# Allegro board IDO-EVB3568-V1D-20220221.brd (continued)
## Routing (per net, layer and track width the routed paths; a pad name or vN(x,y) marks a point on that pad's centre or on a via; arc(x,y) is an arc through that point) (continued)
MIPI_DSI_TX1_D2P: length 65.1
  TOP w0.102: v2(55.63,66.04) 55.88,65.79 61.91,65.79 64.17,68.05 65.56,68.05 66.77,69.26 66.77,69.37 66.39,69.76 M5.131
  BOTTOM w0.102: J23.23 55.5,22.32 55.64,22.46 55.64,23.49 55.52,23.61 D57.7 D57.4 55.52,25.46 55.65,25.6 55.65,25.94 54.86,26.73 54.86,33.5 55.12,33.76 56.13,33.76 56.26,33.88 56.26,34.19 56.13,34.32 55.15,34.32 54.89,34.58 54.89,35.02 55.15,35.28 56.17,35.28 56.41,35.53 56.41,40.29 52.35,44.36 52.35,61.87 54.86,64.39 54.86,65.41 55.27,65.81 55.39,65.81 v2(55.63,66.04)
MIPI_DSI_TX1_D3N: length 64.6
  TOP w0.102: v2(54.36,64.42) 54.6,64.67 62.32,64.67 64.61,66.95 66.95,66.95 69,69 69,69.34 69.39,69.73 M5.128
  BOTTOM w0.102: J23.21 54.5,22.32 54.37,22.46 54.37,23.46 54.52,23.61 D57.9 D57.2 54.52,25.46 54.38,25.6 54.38,35.2 55.88,36.7 55.88,40.07 51.79,44.16 51.79,62.52 53.94,64.67 54.11,64.67 v2(54.36,64.42)
MIPI_DSI_TX1_D3P: length 64.6
  TOP w0.102: M5.129 68.39,69.69 68.77,69.3 68.77,69.1 66.86,67.18 64.52,67.18 62.23,64.9 54.6,64.9 v2(54.36,65.14)
  BOTTOM w0.102: v2(54.36,65.14) 54.11,64.9 53.85,64.9 51.56,62.61 51.56,44.07 55.65,39.98 55.65,36.8 54.15,35.3 54.15,25.6 54.02,25.46 D57.1 D57.10 54.02,23.61 54.14,23.49 54.14,22.46 54.01,22.32 J23.20
MIPI_DSI_TX1_RST: length 6.6
  BOTTOM w0.254: R119.2 62.44,27.39 62.65,27.18 C125.2 62,25.9 J23.36
MIPI_TX0_BL_PWM5: length 4.9
  TOP w0.127: U15.4 14.7,23.29 v2(13.77,23.29)
  BOTTOM w0.127: v2(13.77,23.29) 12.16,23.29 R102.2 R105.1
MIPI_TX1_BL_PWM4: length 2.8
  BOTTOM w0.127: R108.2 R116.1 40.85,34.04 40.93,33.96 U16.4
MPU6500_AD0: length 2.8
  BOTTOM w0.127: 66.4,41.86 R323.2 ; 66.4,41.86 R324.1 ; 66.4,41.86 65.81,41.28 U35.9
NSD_CD: length 6.6
  TOP w0.127: R24.2 118.87,17.96 D8.1 118.84,16.47 119.54,16.47 120.13,15.89 J3.9
PCA9539_A0: length 5.2
  BOTTOM w0.127: U38.21 80.74,44.83 80.74,44.83 R366.1 80.31,44.81 79.76,44.26 78.5,44.26 78.13,44.63 R364.2
PCA9539_A1: length 6.3
  BOTTOM w0.127: R363.2 94.44,48.28 94.07,48.65 92.9,48.65 92.41,48.16 R365.1 91.98,48.13 91.69,47.85 91.69,46.95 90.88,46.13 U38.2
PCA9539_I2C_SCL: length 2.8
  BOTTOM w0.127: R344.2 80.74,45.85 81.11,45.48 U38.22
PCA9539_I2C_SDA: length 2.9
  BOTTOM w0.127: R343.2 80.77,46.86 81.5,46.13 U38.23
PCA9539_INT: length 2.8
  BOTTOM w0.127: U38.1 88.6,46.78 88.44,46.94 R345.2
PCA9539_INT_GPIO4_C4: length 40.8
  TOP w0.127: v2(85.45,37.72) 85.45,35.41 78.87,28.83 70.48,28.83 69.6,27.94 67.31,27.94 65.39,26.02 M5.29
  BOTTOM w0.127: R345.1 87.25,48.13 84.71,45.59 84.71,38.46 v2(85.45,37.72)
PCA9539_IO0_0: length 81.1
  TOP w0.127: R36.1 47.17,78.94 50.55,75.56 v2(51.31,75.56) ; v2(85.1,44.7) 84.71,45.1 84.71,51.56 84.58,51.69 84.58,53.34 85.34,54.1 85.34,61.59 84.33,62.61 77.22,62.61 75.16,64.67 v2(71.04,64.67) ; v2(51.31,73.29) 51.43,73.17 65.55,73.17 66.67,74.3 69.71,74.3 v2(69.85,74.43)
  TOP w0.203: U5.4 48.05,80.44 R36.1
  BOTTOM w0.127: R353.1 92.41,46.08 91.16,44.83 U38.4 85.62,44.83 85.5,44.7 v2(85.1,44.7) ; v2(69.85,74.43) 70.71,73.57 70.71,65 v2(71.04,64.67) ; v2(51.31,73.29) v2(51.31,75.56)
PCA9539_IO0_1: length 18.6
  TOP w0.127: v2(84.61,53.93) 84.33,53.65 84.33,51.54 84.45,51.41 84.45,44.72 v2(85.1,44.07)
  BOTTOM w0.127: R352.1 91.98,45.09 91.08,44.18 U38.5 85.61,44.18 85.5,44.07 v2(85.1,44.07) ; R39.1 v2(84.61,53.93)
PCA9539_IO0_2: length 62
  TOP w0.127: v2(71.5,64.14) 71.78,64.41 75.03,64.41 77.09,62.36 84.2,62.36 85.09,61.47 85.09,55.24 83.95,54.1 83.95,51.56 84.2,51.31 84.2,44.34 v2(85.1,43.43)
  BOTTOM w0.127: v2(71.5,64.14) 73.41,66.04 73.41,73.94 75.77,76.3 75.77,77.98 R40.1 73.06,80.69 U6.4 ; v2(85.1,43.43) 85.5,43.43 85.59,43.53 U38.6 91.44,43.53 91.98,44.07 R351.1
PCA9539_IO0_3: length 54.2
  TOP w0.127: U7.4 80.83,80.37 80.95,80.24 v2(82.4,80.24) ; v2(82.42,59.56) 83.57,58.42 83.57,51.56 83.95,51.18 83.95,43.95 v2(85.1,42.8)
  BOTTOM w0.127: R42.1 81.71,80.01 82.17,80.01 82.27,80.11 ; v2(82.42,59.56) 84.2,61.34 84.2,64.9 85.47,66.17 85.47,67.82 86.49,68.83 86.49,75.31 85.85,75.95 82.93,75.95 82.27,76.61 82.27,80.11 ; v2(85.1,42.8) 85.5,42.8 85.58,42.88 U38.7 91.81,42.88 91.98,43.05 R350.1 ; 82.27,80.11 v2(82.4,80.24)
PCA9539_IO0_4: length 50.7
  TOP w0.127: v2(85.1,42.16) 83.69,43.57 83.69,51.05 82.72,52.03 82.72,58.63 v2(82.42,58.93)
  BOTTOM w0.127: R349.1 91.95,42.04 91.75,42.23 U38.8 85.56,42.23 85.5,42.16 v2(85.1,42.16) ; v2(82.42,58.93) 84.45,60.96 84.45,64.77 85.72,66.04 85.72,67.63 86.74,68.65 86.74,74.8 88.19,76.25 88.19,78.95 88.17,78.98 R47.1 88.17,79.47 87.06,80.58 U9.4
PCA9539_IO0_5: length 53.1
  TOP w0.127: v2(84.99,51.84) 84.99,45.44 85.5,44.93 85.5,41.92 v2(85.11,41.53) ; U10.4 95.2,79.34 R52.1 96.29,78 96.29,78 96.88,78 v2(97.1,78.23)
  BOTTOM w0.127: v2(84.99,51.84) 88.65,55.5 88.65,55.88 89.92,57.15 89.92,60.07 92.46,62.61 92.46,68.07 95.38,70.99 95.38,76.48 95.38,76.69 96.69,78 96.88,78 v2(97.1,78.23) ; R348.1 92.07,41.02 91.52,41.58 U38.9 85.57,41.58 85.53,41.53 v2(85.11,41.53)
PCA9539_IO0_6: length 57.1
  TOP w0.127: 134.03,46.8 134.03,47.45 133.68,47.8 R56.1 ; 134.03,46.8 U11.4 ; 134.03,46.8 v2(132.45,46.8) ; v2(117.47,44.27) 118.29,45.09 126.11,45.09 v2(127.51,43.69)
  BOTTOM w0.127: 92.41,38.96 R347.1 ; 92.41,38.96 91.92,38.48 89.66,38.48 88.9,39.24 88.9,40.83 89,40.93 U38.10 ; 92.41,38.96 92.89,38.48 93.6,38.48 93.98,38.86 93.98,39.5 95,40.51 97.03,40.51 100.46,43.94 110.47,43.94 111.87,42.55 115.06,42.55 115.44,42.16 116.2,42.16 117.47,43.43 v2(117.47,44.27) ; v2(132.45,46.8) 129.34,43.69 v2(127.51,43.69)
PCA9539_IO0_7: length 49.8
  TOP w0.127: v2(104.9,48.64) 104.62,48.92 101.88,48.92 98.02,45.06 v2(98.02,44.35) ; Q13.1 v2(127.14,53.98)
  BOTTOM w0.127: v2(98.02,44.35) 98.02,42.01 97.54,41.53 94.62,41.53 93.6,40.51 92.89,40.51 92.41,40.03 R346.1 92.07,40.01 91.8,40.28 U38.11 ; v2(104.9,48.64) 127.13,48.64 128.02,49.53 128.02,53.09 v2(127.14,53.98)
PCA9539_IO1_0: length 32.2
  TOP w0.127: v2(80.34,33.43) 80.39,33.48 v2(80.39,38.61)
  BOTTOM w0.127: 80.31,39.22 80.39,39.14 v2(80.39,38.61) ; 80.31,39.22 81.64,39.22 82.05,39.63 U38.13 ; 80.31,39.22 R361.1 ; v2(80.34,33.43) 82.52,33.43 85.98,29.97 89.53,29.97 93.34,26.16 93.34,25.02 93.85,24.51 96.9,24.51 98.06,23.36 Q1.1
PCA9539_IO1_1: length 54.8
  TOP w0.127: v2(78.61,38.99) v2(78.61,30.86)
  BOTTOM w0.127: U38.14 82.06,40.28 81.53,39.75 78.96,39.75 78.61,39.41 v2(78.61,38.99) R360.1 ; v2(78.61,30.86) 81.92,30.86 84.84,27.94 87.76,27.94 89.15,26.54 89.15,25.91 89.79,25.27 89.79,24.26 91.57,22.48 91.57,16.89 92.43,16.03 92.43,13.06 91.95,12.57 91.95,11.06 94.5,8.51 100.58,8.51 101.87,9.8 Q2.1
PCA9539_IO1_3: length 115.8
  TOP w0.127: v2(78.99,29.72) 80.9,31.62 v2(80.9,40.51) ; v2(36.32,10.92) 34.72,12.52 R128.1 R126.2 35.77,13.03 36.2,13.46 36.2,14.04 36.38,14.22 Q8.3 ; v2(90.17,12.81) 91.44,11.54 91.44,5.92 89.38,3.86 43.26,3.86 41.15,5.97 v2(41.15,10.79)
  BOTTOM w0.127: v2(90.17,12.81) 90.45,13.09 90.48,13.09 91.06,13.67 91.06,22.23 89.28,24 89.28,25.02 88.65,25.65 88.65,26.29 87.5,27.43 84.58,27.43 82.07,29.95 79.22,29.95 v2(78.99,29.72) ; v2(36.32,10.92) 41.02,10.92 v2(41.15,10.79) ; R358.1 v2(80.9,40.51) 81.97,41.58 U38.16
PCA9539_IO1_4: length 85.3
  TOP w0.127: R382.1 133.68,57.71 134.03,57.36 U40.4 v2(134.03,56.07) ; v2(82.17,38.99) 82.17,40.64 v2(81.15,41.66)
  BOTTOM w0.127: v2(82.17,38.99) 82.42,38.73 82.42,38.59 86.59,34.42 96.52,34.42 96.88,34.77 96.88,35.26 102.18,40.56 104.6,40.56 107.82,37.34 121.28,37.34 121.92,37.97 121.92,41.17 122.68,41.94 130.33,41.94 131.7,43.31 131.7,44.7 133.3,46.3 133.3,48.46 132.89,48.87 132.89,55.68 133.29,56.07 v2(134.03,56.07) ; R357.1 78.61,41.02 78.66,41.07 80.57,41.07 v2(81.15,41.66) 81.73,42.23 U38.17
PCA9539_IO1_5: length 32.4
  TOP w0.127: v2(85.22,38.61) 84.96,38.61 v2(81.03,42.55) ; R342.1 v2(104.19,41.76)
  BOTTOM w0.127: R356.1 81.03,42.37 v2(81.03,42.55) 81.36,42.88 U38.18 ; v2(85.22,38.61) 85.98,38.61 88.77,35.81 95.38,35.81 101.47,41.91 104.01,41.91 104.17,41.76 v2(104.19,41.76)
PCA9539_IO1_6: length 51.2
  TOP w0.127: v2(81.66,37.99) 81.66,40.39 80.52,41.53 80.52,42.8 v2(80.9,43.18)
  BOTTOM w0.127: R379.1 R378.2 84.25,18.48 83.68,19.05 Q17.3 83.4,22.52 81.41,24.51 81.41,26.92 79.5,28.83 77.85,28.83 76.71,29.97 71.75,29.97 71.37,30.35 71.25,30.35 70.1,31.5 70.1,36.45 71.5,37.85 81.13,37.85 81.27,37.99 v2(81.66,37.99) ; R355.1 80.82,43.18 v2(80.9,43.18) 81.25,43.53 U38.19
PCA9539_IO1_7: length 2.8
  BOTTOM w0.127: U38.20 81.14,44.18 80.65,43.69 R354.1
PCA9539_RST: length 5.7
  BOTTOM w0.127: R362.2 94.44,47.01 93.83,47.62 92.89,47.62 92.41,47.14 C269.2 92.41,47.09 91.09,45.77 90.76,45.77 90.46,45.48 U38.3
PCIE20_REFCLKN: length 107.3
  TOP w0.102: v2(71.66,33.02) 71.88,33.24 71.88,33.43 71.75,33.55 52.74,33.55 50.85,35.44 50.85,52.4 50.09,53.16 38.28,53.16 36.74,51.62 36.15,51.62 35.77,51.24 M5.178 ; R331.2 113.14,19.53 113.04,19.43 113.04,19.12 v2(113.29,18.87)
  BOTTOM w0.102: v2(113.29,18.87) 113.04,19.12 113.04,22.28 112.74,22.58 105.89,22.58 101.8,26.67 93.85,26.67 89.79,30.73 86.36,30.73 82.8,34.29 72.68,34.29 71.88,33.5 71.88,33.24 v2(71.66,33.02)
PCIE20_REFCLKP: length 107.3
  TOP w0.102: v2(112.57,18.87) 112.81,19.12 112.81,19.43 112.71,19.53 R328.2 ; v2(72.38,33.02) 72.11,33.29 72.11,33.52 71.85,33.78 52.83,33.78 51.08,35.53 51.08,52.49 50.18,53.39 38.18,53.39 36.64,51.85 36.18,51.85 35.8,52.24 M5.177
  BOTTOM w0.102: v2(72.38,33.02) 72.11,33.29 72.11,33.4 72.77,34.06 82.71,34.06 86.27,30.51 89.69,30.51 93.76,26.44 101.7,26.44 105.79,22.35 112.65,22.35 112.81,22.19 112.81,21.71 112.69,21.58 112.69,21.28 112.81,21.15 112.81,20.84 112.69,20.72 112.69,20.41 112.81,20.28 112.81,19.98 112.69,19.85 112.69,19.55 112.81,19.42 112.81,19.12 v2(112.57,18.87)
PCIE20_RXN: length 115.4
  TOP w0.102: R333.2 117.35,19.26 117.35,17.96 116.68,17.3 114.42,17.3 v2(114.17,17.05) ; v2(71.16,34.29) 71.4,34.53 71.4,34.65 71.22,34.82 52.86,34.82 51.69,36 51.69,53.09 50.5,54.28 37.81,54.28 37.16,53.62 36.2,53.62 35.81,53.24 M5.176
  BOTTOM w0.102: v2(71.16,34.29) 71.4,34.53 71.4,34.77 71.69,35.05 83.06,35.05 86.64,31.47 90.01,31.47 94.18,27.3 102.18,27.3 106.14,23.34 114.2,23.34 114.94,22.61 114.94,17.58 114.66,17.3 114.42,17.3 v2(114.17,17.05)
PCIE20_RXN_: length 2.9
  TOP w0.127: R333.1 117.14,20.83 117.14,20.96 116.57,21.53 116.57,21.71 116.69,21.83 U36.41
PCIE20_RXP: length 115.4
  TOP w0.102: v2(71.87,34.29) 71.63,34.53 71.63,34.74 71.32,35.05 52.96,35.05 51.92,36.09 51.92,53.18 50.59,54.51 37.72,54.51 37.06,53.85 36.2,53.85 35.81,54.24 M5.175 ; R332.2 117.12,18.98 117.12,18.06 116.59,17.53 114.42,17.53 v2(114.17,17.77)
  BOTTOM w0.102: v2(71.87,34.29) 71.63,34.53 71.63,34.67 71.78,34.82 82.96,34.82 86.54,31.24 89.92,31.24 94.08,27.08 102.08,27.08 106.04,23.11 114.1,23.11 114.71,22.51 114.71,21.2 114.6,21.09 114.53,21.09 114.43,20.99 114.43,20.79 114.53,20.69 114.6,20.69 114.71,20.59 114.71,20.38 114.6,20.28 114.53,20.28 114.43,20.18 114.43,19.98 114.53,19.88 114.6,19.88 114.71,19.77 114.71,19.57 114.6,19.47 114.53,19.47 114.43,19.37 114.43,19.16 114.53,19.06 114.6,19.06 114.71,18.96 114.71,17.67 114.56,17.53 114.42,17.53 v2(114.17,17.77)
PCIE20_RXP_: length 2.8
  TOP w0.127: R332.1 116.89,20.67 116.89,20.85 116.32,21.42 116.32,21.71 116.19,21.83 U36.43
PCIE20_TXN: length 113.1
  TOP w0.102: v2(116.33,18.91) 116.09,18.67 115.28,18.67 115.18,18.77 115.18,19.12 C251.2 ; M5.174 35.81,55.24 36.19,55.62 50.42,55.62 52.58,53.47 52.58,36.45 53.06,35.97 71.15,35.97 71.27,35.84 71.27,35.68 v2(71.03,35.43)
  BOTTOM w0.102: v2(116.33,18.91) 116.09,18.67 115.94,18.67 115.67,18.94 115.67,20.28 115.82,20.43 115.82,20.69 115.67,20.84 115.67,21.09 115.82,21.25 115.82,21.5 115.67,21.65 115.67,21.91 115.82,22.06 115.82,22.31 115.67,22.47 115.67,23.27 114.17,24.77 106.17,24.77 103,27.94 94.49,27.94 90.2,32.23 86.84,32.23 82.9,36.17 71.53,36.17 ; v2(71.03,35.43) 71.27,35.68 71.27,35.91 ; 71.53,36.17 71.53,36.17 71.27,35.92 71.27,35.91 ; 71.53,36.17 71.27,35.91
PCIE20_TXN_: length 2.7
  TOP w0.127: C251.1 115.19,20.75 115.19,21.41 115.07,21.53 115.07,21.71 115.19,21.83 U36.47
PCIE20_TXP: length 113.2
  TOP w0.102: C249.2 114.95,19.12 114.95,18.68 115.18,18.44 116.09,18.44 v2(116.33,18.2) ; M5.173 35.84,56.24 36.22,55.85 50.52,55.85 52.81,53.56 52.81,36.54 53.16,36.2 71.24,36.2 71.5,35.93 71.5,35.68 v2(71.74,35.43)
  BOTTOM w0.102: v2(116.33,18.2) 116.09,18.44 115.85,18.44 115.44,18.85 115.44,23.17 114.08,24.54 106.08,24.54 102.9,27.71 94.39,27.71 90.1,32 86.74,32 82.8,35.94 75.95,35.94 75.82,35.81 75.51,35.81 75.39,35.94 75.08,35.94 74.96,35.81 74.65,35.81 74.52,35.94 74.22,35.94 74.09,35.81 73.79,35.81 73.66,35.94 73.36,35.94 73.23,35.81 72.92,35.81 72.8,35.94 72.49,35.94 72.36,35.81 72.06,35.81 71.93,35.94 71.63,35.94 71.5,35.81 71.5,35.68 v2(71.74,35.43)
PCIE20_TXP_: length 2.7
  TOP w0.127: C249.1 114.94,20.75 114.94,21.3 114.82,21.42 114.82,21.71 114.69,21.83 U36.49
PHY0_CLKOUT125: length 2.5
  BOTTOM w0.127: R193.2 103.12,70.87 103.23,70.76 103.95,70.76 104.04,70.67 U24.35
PHY0_G_LED-: length 27.4
  TOP w0.152: v2(98.42,86.11) 98.93,85.6 R192.1
  TOP w0.203: J30.12 111.78,98.57 100.51,87.3 v2(100.51,87.21)
  BOTTOM w0.203: v2(98.42,86.11) 99.4,86.11 v2(100.51,87.21)
PHY0_LED0/CFG_EXT: length 2.7
  TOP w0.254: v2(103.84,69.47) 104.14,69.16 R195.2 103.86,68.61 103.73,68.61 R196.1
  BOTTOM w0.203: v2(103.84,69.47) U24.32
PHY0_LED1/CFG_LDO0: length 43.7
  TOP w0.152: v2(100.33,87.74) 100.52,87.74 110.87,98.09 110.87,99.06 111.76,99.95 113.45,99.95 J30.11 ; v2(98.42,86.74) 99.44,85.72 99.44,79.96 C173.2 R203.2 99.57,77.52 99.57,74.04 102.56,71.05 v2(102.56,70.36)
  BOTTOM w0.152: v2(100.33,87.74) 99.33,86.74 v2(98.42,86.74) ; U24.33 104.01,69.87 103.96,69.92 103.57,69.92 103.12,70.36 v2(102.56,70.36)
PHY0_LED2/CFG_LDO1: length 38.4
  TOP w0.152: J30.13 102.74,99.95 101.22,99.95 100.3,99.03 100.3,95.86 97.79,93.35 97.79,88.47 100.58,85.67 100.58,75.49 102.41,73.66 102.41,72.72 C172.2
  TOP w0.203: C172.2 R200.1 103.67,70.37 v2(103.78,70.37) 103.91,70.37 103.95,70.41 R199.2
  BOTTOM w0.203: v2(103.78,70.37) 103.89,70.27 U24.34
PHY0_MDI0+: length 3.6
  BOTTOM w0.102: U24.1 105.03,73.54 105.12,73.62 105.12,73.81 105.02,73.91 103.63,73.91 103.39,74.16 103.39,74.69 R190.1
PHY0_MDI0-: length 3.6
  BOTTOM w0.102: U24.2 105.43,73.51 105.35,73.6 105.35,73.91 105.11,74.14 103.73,74.14 103.62,74.25 103.62,74.69 R189.1
PHY0_MDI1+: length 2.7
  BOTTOM w0.102: U24.4 106.23,73.59 106.32,73.68 106.32,74.15 106.17,74.3 105.76,74.3 105.52,74.53 105.52,74.69 R188.1
PHY0_MDI1-: length 2.7
  BOTTOM w0.102: U24.5 106.63,73.58 106.55,73.67 106.55,74.24 106.27,74.52 105.85,74.52 105.75,74.63 105.75,74.69 R187.1
PHY0_MDI2+: length 2.5
  BOTTOM w0.102: R186.1 107.66,74.69 107.66,74.55 107.56,74.45 107.35,74.45 107.09,74.18 107.09,73.57 107.09,73.56 107.03,73.5 U24.6
PHY0_MDI2-: length 2.5
  BOTTOM w0.102: R185.1 107.89,74.69 107.89,74.45 107.65,74.22 107.44,74.22 107.31,74.09 107.31,73.66 107.43,73.54 U24.7
PHY0_MDI3+: length 3.2
  BOTTOM w0.102: R184.1 109.63,75.11 109.73,75.01 109.73,74.8 109.63,74.7 109.62,74.7 109.47,74.55 108.9,74.55 108.32,73.97 108.32,73.57 108.23,73.48 U24.9
PHY0_MDI3-: length 3.1
  BOTTOM w0.102: R183.1 110.03,74.7 109.96,74.7 109.72,74.47 109.72,74.47 109.57,74.32 108.99,74.32 108.55,73.88 108.55,73.57 108.63,73.48 U24.10
PHY0_RSTN: length 59.8
  TOP w0.127: v2(110.49,72.27) 110.69,72.47 111.28,72.47 111.41,72.34 ; 111.41,72.34 110.85,71.78 v2(110.85,70.43) ; 111.41,72.34 R218.2 ; v2(76,74.96) 77.24,74.96 77.98,75.69 88.09,75.69 89.61,74.17 94.54,74.17 100.08,68.63 100.08,63.88 101.85,62.1 v2(101.85,61.61)
  BOTTOM w0.127: v2(76,74.96) 75.44,74.4 R219.2 ; C182.2 110.56,72.34 v2(110.49,72.27) U24.12 ; v2(110.85,70.43) 111.43,69.85 111.43,65.41 107.49,61.47 101.99,61.47 v2(101.85,61.61)
PHY0_RXCLK/PHYAD1: length 7.3
  TOP w0.127: v2(105.79,67.13) 105.62,67.13 R209.1
  BOTTOM w0.127: U24.27 106.23,68.11 106.1,67.97 106.1,67.31 105.92,67.13 v2(105.79,67.13) 104.34,67.13 103.25,66.04 R208.2 C496.2 101.81,65.99 101.73,65.91 R227.1
PHY0_RXD0/RXDLY: length 5
  TOP w0.127: R210.2 107.01,68.43 v2(107.01,67.92) 107.01,66.97 R211.1
  BOTTOM w0.127: R223.1 105.61,65.96 107.01,67.36 v2(107.01,67.92) 107.01,67.94 107.03,67.97 U24.25
PHY0_RXD1/TXDLY: length 5.2
  TOP w0.127: R213.2 107.91,68.56 107.42,68.06 v2(107.42,67.49) 107.47,67.44 107.47,67.38 R214.1
  BOTTOM w0.127: R224.1 106.45,65.96 106.93,66.45 106.93,66.8 107.42,67.28 v2(107.42,67.49) 107.42,68.5 U24.24
PHY0_RXD2/PLLOFF: length 6.3
  TOP w0.127: R217.1 108.71,66.93 108.3,67.34 108.27,67.34 108.26,67.35 108.22,67.35 108.21,67.36 108.03,67.36 107.82,67.56 v2(107.82,67.91) 108.04,68.13 108.26,68.13 108.44,68.13 108.55,68.24 108.55,68.88 R216.2
  BOTTOM w0.127: R225.1 107.44,66.9 107.82,67.28 v2(107.82,67.91) 107.83,67.92 U24.23
PHY0_RXD3/PHYAD0: length 3.7
  TOP w0.127: v2(108.37,67.74) 108.37,67.73 108.74,67.36 109.35,67.36 109.78,66.93 R207.1
  BOTTOM w0.127: R226.1 108.46,67.65 v2(108.37,67.74) 108.36,67.75 108.36,67.92 108.23,68.04 U24.22
PHY0_RXDV/PHYAD2: length 5.1
  TOP w0.127: R206.2 106.15,68.3 106.5,67.94 v2(106.5,67.61)
  BOTTOM w0.127: R228.1 104.42,65.96 104.79,66.33 104.96,66.33 105.13,66.5 105.77,66.5 106.5,67.23 v2(106.5,67.61) 106.5,67.92 106.63,68.05 U24.26
PHY0_XTALIN: length 8.3
  BOTTOM w0.152: 102.03,71.91 102.05,71.88 102.74,71.88 103.49,71.14 104.1,71.14 104.17,71.07 U24.36 ; 102.03,71.91 101.98,71.91 101.5,72.39 100.58,72.39 100.08,72.9 97.92,72.9 97.7,72.68 XT4.3 ; 102.03,71.91 C169.2
PHY0_XTALOUT: length 7.3
  BOTTOM w0.152: U24.37 103.67,71.47 102.03,73.1 C170.2 101.55,72.67 100.85,72.67 100.72,72.8 100.72,72.81 99.4,74.13 XT4.1
PHY0_Y_LED+: length 23.4
  TOP w0.152: R191.1 101.02,78.23 101.02,85.8 98.12,88.7 98.12,93.17 101.58,96.63 J30.14
PHY1_CLKOUT125: length 2.5
  BOTTOM w0.127: R240.2 117.14,68.88 117.32,69.06 117.8,69.06 117.87,68.99 U25.35
PHY1_G_LED-: length 7.7
  TOP w0.203: J31.12 134.05,96.77 137.03,96.77 R239.1
PHY1_LED0/CFG_EXT: length 3
  TOP w0.127: R243.1 116.73,67.07 116.73,67.25 R242.2 117.19,67.72 v2(117.5,67.72)
  BOTTOM w0.127: v2(117.5,67.72) 117.57,67.79 U25.32
PHY1_LED1/CFG_LDO0: length 51.7
  TOP w0.203: J31.11 133.42,99.95 127.79,99.95 125.96,98.12 125.96,92.38 120.45,86.87 116.85,86.87 116.43,86.45 116.43,82.4 113.41,79.38 113.41,74.68 114.3,73.79 114.3,69.72 114.81,69.22 115.47,69.22 C196.2 116.57,68.11 v2(116.59,68.11)
  BOTTOM w0.203: U25.33 116.66,68.19 v2(116.59,68.11) 116.29,67.82 R250.2
PHY1_LED2/CFG_LDO1: length 41.4
  TOP w0.203: J31.13 125.32,97.33 125.32,92.51 120.31,87.49 117.09,87.49 v2(117.06,87.53) ; C195.2 118.42,68.71 118.35,68.64 v2(117.66,68.64) 116.98,68.64 116.08,69.55 R246.2 116.08,70.87 114.81,72.14 114.81,73.91 v2(113.92,74.8) 113.92,79.38 117.06,82.51 v2(117.06,86.19)
  BOTTOM w0.203: v2(117.06,86.19) v2(117.06,87.53) ; R247.1 113.59,74.55 113.67,74.55 v2(113.92,74.8) ; v2(117.66,68.64) 117.71,68.59 U25.34
PHY1_MDI0+: length 2.6
  BOTTOM w0.102: U25.1 119.05,72.05 119.14,72.14 119.14,72.24 119.04,72.34 118.82,72.34 118.75,72.26 118.42,72.26 118.24,72.45 118.24,72.65 R237.1
PHY1_MDI0-: length 2.5
  BOTTOM w0.102: R236.1 118.47,72.7 118.47,72.54 118.52,72.49 118.65,72.49 118.73,72.57 119.14,72.57 119.37,72.34 119.37,72.14 119.45,72.05 U25.2
PHY1_MDI1+: length 2
  BOTTOM w0.102: U25.4 120.25,72.05 120.34,72.14 120.34,72.5 120.22,72.63 120.22,72.95 R235.1
PHY1_MDI1-: length 2
  BOTTOM w0.102: R234.1 120.45,72.98 120.45,72.72 120.57,72.6 120.57,72.14 120.65,72.05 U25.5
PHY1_MDI2+: length 2.8
  BOTTOM w0.102: R233.1 122.2,72.9 122.2,72.84 122.1,72.75 121.55,72.75 121.14,72.34 121.14,72.14 121.05,72.05 U25.6
PHY1_MDI2-: length 2.8
  BOTTOM w0.102: U25.7 121.45,72.05 121.37,72.14 121.37,72.24 121.64,72.52 122.2,72.52 122.43,72.75 122.43,72.93 R232.1
PHY1_MDI3+: length 3.5
  BOTTOM w0.102: U25.9 122.25,71.85 122.34,71.93 122.34,72.07 122.61,72.34 123.83,72.34 124.31,72.81 124.31,72.93 R231.1
PHY1_MDI3-: length 3.5
  BOTTOM w0.102: U25.10 122.65,71.81 122.57,71.89 122.57,71.98 122.7,72.11 123.93,72.11 124.54,72.72 124.54,72.9 R230.1
PHY1_RSTN: length 125.5
  TOP w0.127: R266.2 124.28,70.82 ; 124.28,70.82 124.05,70.59 v2(123.85,70.59) ; 124.28,70.82 124.28,70.49 124.33,70.44 C207.2 ; v2(78.74,50.16) 82.17,46.74 82.17,43.43 85.22,40.39 v2(85.7,40.39)
  BOTTOM w0.127: R267.2 70.1,63.25 74.68,58.67 74.68,52.45 76.96,50.16 v2(78.74,50.16) ; U25.12 v2(123.85,70.59) 124.08,70.82 124.08,71.5 124.66,72.09 125.07,72.09 125.4,71.75 126.11,71.75 129.08,68.78 129.08,67.36 132.59,63.86 132.59,48.56 132.97,48.18 132.97,46.51 129.59,43.13 119.23,43.13 116.99,40.89 114.81,40.89 114.43,41.27 110.74,41.27 109.35,42.67 101.09,42.67 95,36.58 89.51,36.58 v2(85.7,40.39)
PHY1_RXCLK/PHYAD1: length 5.4
  BOTTOM w0.127: U25.27 120.25,65.85 R255.1 119.56,65.07 118.7,64.21 C497.2 118.7,63.68 118.75,63.63 R254.2 R275.1
PHY1_RXD0/RXDLY: length 3.5
  TOP w0.127: R258.1 120.78,65.84 v2(121.05,66.12) 121.31,66.37 121.31,66.85 R257.2
  BOTTOM w0.127: U25.25 v2(121.05,66.12) 121.05,65.79 121.64,65.2 R271.1
PHY1_RXD1/TXDLY: length 5.8
  TOP w0.127: R261.1 121.79,65.91 v2(121.69,66.01) 122.3,66.62 R260.2
  BOTTOM w0.127: R272.1 122.91,63.29 122.3,63.91 122.3,65.41 v2(121.69,66.01) 121.45,66.25 U25.24
PHY1_RXD2/PLLOFF: length 4.3
  TOP w0.127: R264.1 122.76,65.5 v2(122.38,65.89) 122.38,66.17 122.91,66.7 123.14,66.7 R263.2
  BOTTOM w0.127: R273.1 122.94,65.53 122.58,65.89 v2(122.38,65.89) 121.85,66.41 U25.23
PHY1_RXD3/PHYAD0: length 3.7
  TOP w0.127: v2(122.94,66.17) 122.96,66.17 123.62,65.5 R251.1
  BOTTOM w0.127: R274.1 123.93,65.2 123.56,65.57 123.53,65.57 v2(122.94,66.17) 122.81,66.29 122.48,66.29 122.25,66.52 U25.22
PHY1_RXDV/PHYAD2: length 3.8
  BOTTOM w0.127: U25.26 120.65,65.76 120.65,65.75 R256.2 120.67,65.2 121.16,64.72 121.16,64.08 121.28,63.96 R276.1
PHY1_XTALIN: length 7.5
  BOTTOM w0.152: XT5.3 113.45,71.03 113.92,71.5 115.77,71.5 C192.2 116.55,70.95 116.76,70.95 116.92,70.8 116.92,70.08 117.53,69.47 118.19,69.47 118.27,69.39 U25.36
PHY1_XTALOUT: length 5.5
  BOTTOM w0.152: U25.37 117.69,69.79 117.2,70.28 117.2,71.02 116.43,71.78 C193.2 115.59,71.86 115.15,72.3 XT5.1
PHY1_Y_LED+: length 34.1
  TOP w0.203: J31.14 116.73,98.57 114.55,96.39 112.52,96.39 111.12,95 111.12,91.69 115.95,86.87 115.95,82.42 112.9,79.38 v2(112.9,76.5)
  BOTTOM w0.203: v2(112.9,76.5) 112.65,76.25 R238.1
PWM7_IR: length 127
  TOP w0.127: v2(68.83,29.59) 67.44,29.59 65.15,27.3 63.55,27.3 61.39,25.15 M5.25 ; v2(70.74,21.97) 70.99,21.72 89.41,21.72 89.92,21.21 97.79,21.21 100.08,23.5 100.08,30.48 100.97,31.37 100.97,42.55 103.38,44.96 116.06,44.96 116.18,45.09 116.2,45.09 117.47,46.35 128.22,46.35 129.29,45.29 129.29,38.86 132.41,35.74 132.41,32.44 137.82,27.02 D102.1 139.14,27.02 J14.7
  BOTTOM w0.127: v2(70.74,21.97) 70.99,22.23 70.99,27.43 v2(68.83,29.59)
REFCLK_GM8775C: length 2.5
  TOP w0.203: R125.1 19.81,28.41 U17.24
REFCLKN_: length 2.8
  TOP w0.127: U36.53 113.7,21.83 113.57,21.71 113.57,21.42 113.09,20.94 113.09,20.76 R331.1
REFCLKP_: length 2.8
  TOP w0.127: U36.55 113.19,21.83 113.32,21.71 113.32,21.53 112.84,21.05 112.84,20.84 R328.1
REXT: length 3.6
  BOTTOM w0.127: R54.1 87.38,65.28 87.38,64.8 87.1,64.52 87.1,64.24 86.48,63.62 U8.27
RK809_PWRON: length 142.9
  TOP w0.127: v2(97.05,21.95) 97.21,22.1 97.79,22.1 99.57,23.88 99.57,30.73 100.46,31.62 100.46,42.8 103.12,45.47 115.82,45.47 117.22,46.86 128.53,46.86 129.79,45.6 129.79,41.15 131.04,39.91 D34.1 134.11,36.45 137.67,32.89 J13.2 ; v2(71.12,32.84) 71.04,32.77 50.93,32.77 50.67,32.51 50.67,26.54 48.67,24.54 44.86,24.54 44.39,24.07 M5.8
  BOTTOM w0.127: v2(71.12,32.84) 71.12,32.31 72.44,30.99 73.79,30.99 74.8,32 82.04,32 85.34,28.7 88.9,28.7 92.08,25.53 92.08,24.38 93.22,23.24 95.76,23.24 v2(97.05,21.95)
RK809_VDC: length 15.7
  TOP w0.203: v2(49.83,29.13) 49.83,26.64 48.34,25.15 43.18,25.15 42.39,24.36 42.39,23.57 M5.6
  BOTTOM w0.203: R7.2 50.7,31.72 R10.1 C14.2 50.72,30.33 49.83,29.44 v2(49.83,29.13)
RS485_5_DM: length 2.9
  TOP w0.127: U29.7 15.04,53.01 v2(15.11,53.09)
  BOTTOM w0.127: R289.2 14.91,52.88 v2(15.11,53.09) 15.16,53.04 L42.1
RS485_5_DP: length 2.8
  TOP w0.127: U29.6 v2(15.04,54.28)
  BOTTOM w0.127: R292.1 14.91,54.41 v2(15.04,54.28) 15.16,54.41 L43.1
RS485_5_RW_EN: length 3.9
  TOP w0.254: R293.1 20.28,53.52 v2(20.13,53.66) ; v2(20.13,53.66) 19.48,53.01 U29.2 ; v2(20.13,53.66) 19.51,54.28 U29.3
  BOTTOM w0.254: v2(20.13,53.66) 20,53.79 U28.4
RS485_7_DM: length 3.2
  TOP w0.127: U31.7 15,47.37 v2(15.38,47.75)
  BOTTOM w0.203: L44.1 15.98,47.15 v2(15.38,47.75) 14.82,47.75 R296.2
RS485_7_DP: length 3
  TOP w0.127: U31.6 15.24,48.64 v2(15.37,48.51)
  BOTTOM w0.203: R298.1 15.33,48.51 v2(15.37,48.51) 15.49,48.39 L45.1
RS485_7_RW_EN: length 6.3
  TOP w0.254: v2(21.59,50.55) 21.51,50.62 R299.1 20.83,49.28 20.19,48.64 U31.3 U31.2
  BOTTOM w0.254: v2(21.59,50.55) 21.8,50.34 U30.4
RSET0: length 3.4
  BOTTOM w0.127: U24.39 104.08,72.27 104.04,72.31 103.84,72.31 102.03,74.12 R212.2
RSET1: length 1.4
  TOP w0.127: R259.2 117.75,70.89 v2(117.78,70.87)
  BOTTOM w0.127: v2(117.78,70.87) 117.81,70.87 118.08,70.59 U25.39
RTCIC_32KOUT: length 6
  TOP w0.127: U34.7 116.67,41.99 115.95,41.27 115.49,41.27 114.48,40.26 114.05,40.26 113.28,41.02 R177.1
S0RX: length 24.6
  BOTTOM w0.203: R383.2 12.55,57.74 12.47,57.82
  BOTTOM w0.254: F14.1 6.52,73.21 D103.2 7.99,72.63 7.75,72.39 5.33,72.39 4.7,71.75 4.7,64.9 5.74,63.86 7.36,63.86 12.47,58.74 L41.2 12.47,57.82
S0RX_: length 23.8
  TOP w0.254: J32.3 9.93,83.91 10.54,83.29 10.54,75.18 9.27,73.91 4.83,73.91 4.45,74.3 v2(4.45,74.42)
  BOTTOM w0.254: TP3.1 3.58,75.16 3.71,75.16 v2(4.45,74.42) 4.45,73.79 4.19,73.53 F14.2
S0TX: length 20.6
  BOTTOM w0.254: 12.47,60.01 L40.2 ; 12.47,60.01 12.08,60.01 7.44,64.64 5.96,64.64 5.21,65.4 5.21,69.6 5.46,69.85 7.11,69.85 7.99,70.73 D103.1 6.39,71.31 F15.1 ; 12.47,60.01 12.47,61.04 R278.2
S0TX_: length 21.1
  TOP w0.254: J32.2 9.66,81.91 10.03,81.53 10.03,75.44 9.02,74.42 v2(5.08,74.42)
  BOTTOM w0.254: TP2.1 4.95,74.55 v2(5.08,74.42) 5.08,73.2 3.2,71.32 F15.2
S3RX_M1: length 13.9
  BOTTOM w0.203: R384.2 18.06,69.49 17.24,69.49 16.58,70.15 15.49,70.15 15.14,69.8 L35.2 15.14,69.4 14.42,68.68 8.88,68.68 8.58,68.39 D78.2
  BOTTOM w0.254: D78.2 6.47,68.39 F2.1
S3RX_M1_: length 13.2
  TOP w0.254: v2(1.84,70.95) J33.3
  BOTTOM w0.254: TP4.1 4.19,63.88 4.19,67.46 3.22,68.43 F2.2 3.22,68.83 1.84,70.21 v2(1.84,70.95)
S3TX_M1: length 13.3
  BOTTOM w0.203: D78.1 7.87,67 9.06,68.2 L34.2 15.14,67.87 15.52,67.49 17.4,67.49 R282.2
  BOTTOM w0.254: F3.1 6.52,66.49 D78.1
S3TX_M1_: length 9.6
  TOP w0.254: v2(1.84,68.95) J33.2
  BOTTOM w0.254: v2(1.84,68.95) 1.84,67.77 3.22,66.39 F3.2 3.22,64.81 3.17,64.76 TP5.1
S4RX_M1: length 23.4
  TOP w0.203: v2(17.76,65.81) v2(16.79,65.81)
  BOTTOM w0.203: v2(16.79,65.81) 16.51,65.81 L37.2 18.34,63.17 18.34,60.88 16.99,59.54 16.99,57.38 16.38,56.77 11.86,56.77 10.87,57.76 8.21,57.76 D81.2 ; R385.2 v2(17.76,65.81)
  BOTTOM w0.254: F4.1 6.47,57.97 D81.2
S4RX_M1_: length 6.7
  TOP w0.254: J34.3 4.9,58 4.65,57.74 v2(4.65,57.02)
  BOTTOM w0.254: TP6.1 3.17,59.35 3.22,59.3 F4.2 4.39,58.22 4.65,57.96 v2(4.65,57.02)
S4TX_M1: length 24.3
  BOTTOM w0.203: D81.1 8.71,56.07 9.02,56.39 16.76,56.39 17.4,57.02 17.4,59.36 18.75,60.71 18.75,63.32 17.26,64.81 17.26,66.07 R284.2 17.6,66.67 L36.2
  BOTTOM w0.254: F5.1 6.52,56.07 D81.1
S4TX_M1_: length 6.9
  TOP w0.254: v2(5.21,57.02) 5.21,56.25 5.46,56 J34.2
  BOTTOM w0.254: v2(5.21,57.02) 5.21,56.03 4.95,55.78 F5.2 3.22,54.7 3.17,54.65 TP7.1
S5RX_M1: length 1.9
  TOP w0.127: U29.1 v2(20.17,51.74)
  BOTTOM w0.127: D82.C 20.62,52.2 v2(20.17,51.74)
S5RX_M1/RS485-A5: length 32.3
  TOP w0.127: v2(15.37,44.88) 15.67,45.19 16.48,45.19 17.98,46.69 17.98,48.31 16,50.29 16,53.21 16.51,53.72 v2(16.51,55.24) 15.62,56.13 v2(15.62,61.8)
  BOTTOM w0.127: L39.2 16.28,61.44 15.93,61.8 v2(15.62,61.8) ; v2(16.51,55.24) 16.61,55.24 16.94,54.92 L43.2
  BOTTOM w0.203: R290.2 13.82,45.39 13.47,45.74 D75.C 11.49,44.7 8.31,44.7 D85.2
  BOTTOM w0.254: F6.1 7.06,45.26 7.3,45.02 D85.2
  BOTTOM w0.508: R290.2 15.37,45.37 v2(15.37,44.88)
S5RX_M1_: length 6.7
  TOP w0.254: v2(4.65,44.07) 4.65,44.74 4.95,45.04 J35.3
  BOTTOM w0.254: v2(4.65,44.07) 4.65,45.01 4.39,45.26 F6.2 3.22,46.34 3.17,46.39 TP8.1
S5TX_M1: length 3.8
  TOP w0.254: U29.4 v2(17.98,55.55)
  BOTTOM w0.254: R286.2 v2(17.98,55.55)
S5TX_M1/RS485-B5: length 34.5
  TOP w0.127: v2(15.75,62.74) 16.03,62.46 16.03,56.36 16.94,55.45 v2(16.94,53.67) 16.66,53.39 16.66,53.36 16.31,53.01 16.31,50.37 18.29,48.39 18.29,46.99 18.24,46.94 18.24,46.58 16.56,44.91 16.03,44.91 v2(15.42,44.3)
  BOTTOM w0.127: L38.2 v2(15.75,62.74) ; v2(16.94,53.67) L42.2
  BOTTOM w0.152: v2(15.42,44.3) 15.42,42.67 R290.1
  BOTTOM w0.203: R290.1 15.31,42.62 13.3,42.62 D75.A 12.14,41.84 10.86,43.12 D85.1
  BOTTOM w0.254: D85.1 7.43,43.12 7.14,42.82 F7.1
S5TX_M1_: length 6.8
  TOP w0.254: J35.2 5.46,43.04 5.21,43.3 v2(5.21,44.07)
  BOTTOM w0.254: TP9.1 3.17,41.7 3.22,41.75 F7.2 4.95,42.82 5.21,43.08 v2(5.21,44.07)
S7RX_M1: length 1.6
  TOP w0.127: v2(20.19,45.97) 20.07,46.1 U31.1
  BOTTOM w0.127: v2(20.19,45.97) 20.24,45.92 D86.C
S7RX_M1/RS485-A7: length 26
  BOTTOM w0.203: F8.1 6.1,32.23 9.6,32.23 D87.2 10.75,34.38 11.41,35.03 R297.2 11.41,37.7 12.06,38.35 D104.C 12.41,38.51 15.95,38.51 16.87,39.42 16.87,45.72 17.96,46.81 17.96,47.57 17.53,48.01 17.32,48.01 L45.2
S7RX_M1_: length 5.6
  TOP w0.203: J36.3 4.99,32.09 v1(3.96,31.06)
  BOTTOM w0.203: TP10.1 3.96,30.81 v1(3.96,31.06) 3.02,32.01 F8.2
S7TX_M1: length 2.4
  TOP w0.127: U31.4 v2(17.78,49.91)
  BOTTOM w0.127: R291.2 17.4,49.53 v2(17.78,49.91)
S7TX_M1/RS485-B7: length 25.5
  BOTTOM w0.203: F9.1 7.56,33.38 D87.1 8.85,35.24 R297.1 8.61,38.11 D104.A 9.66,39.65 13.18,39.65 13.94,38.89 15.77,38.89 16.54,39.65 16.54,46 16.94,46.4 L44.2
S7TX_M1_: length 8.7
  TOP w0.203: J36.2 5.44,30.09 4.87,30.67 4.87,31.03 v1(4.88,31.04)
  BOTTOM w0.203: TP11.1 3.07,34.88 F9.2 4.88,33.07 v1(4.88,31.04)
SARADC_VIN0_KEY/RECOVERY: length 175.4
  TOP w0.127: v1(139.83,68.07) 130.38,68.07 129.39,67.08 129.39,48.36 128.91,47.88 116.74,47.88 115.34,46.48 102.62,46.48 99.44,43.31 99.44,32.13 98.55,31.24 98.55,24.38 97.66,23.5 96.82,23.5 v2(96.44,23.11) ; v1(136.14,83.44) 136.93,83.44 138.43,84.94 141.58,84.94 143.89,87.25 143.89,93.85 143.38,94.36 141.73,94.36 141.25,94.84 D33.1 141.25,96.27 R62.1 ; M5.15 51.39,24.21 58.93,31.75 70.48,31.75 70.76,32.03 v2(72.14,32.03)
  BOTTOM w0.127: v1(136.14,83.44) 135.64,82.93 135.64,76.48 139.83,72.29 v1(139.83,68.07) ; v2(72.14,32.03) 72.82,31.34 73.76,31.34 74.68,32.26 82.17,32.26 85.47,28.96 89.03,28.96 92.33,25.65 92.33,24.51 93.34,23.5 96.06,23.5 v2(96.44,23.11)
SARADC_VIN2_HP_HOOK: length 148
  TOP w0.127: J13.3 136.27,34.92 135,36.2 135,38.23 135.51,38.73 D35.1 134.87,40.54 134.87,41.53 134.62,41.78 132.59,41.78 131.83,41.02 130.43,41.02 130.05,41.4 130.05,45.87 128.8,47.12 117.12,47.12 115.72,45.72 103,45.72 100.2,42.93 100.2,31.75 99.31,30.86 99.31,24 97.66,22.35 96.7,22.35 v2(96.39,22.05) 95.96,21.62 v2(90.63,21.62) ; M5.16 52.39,24.7 59.05,31.37 70.89,31.37 v2(71.12,31.6)
  TOP w0.254: R70.2 R71.1 C81.2 87.6,16.94 v2(87.43,16.76)
  BOTTOM w0.127: v2(96.39,22.05) 95.45,22.99 93.09,22.99 91.82,24.26 91.82,25.4 88.77,28.45 85.22,28.45 81.92,31.75 74.93,31.75 73.91,30.73 71.98,30.73 v2(71.12,31.6)
  BOTTOM w0.254: v2(90.63,21.62) 88.85,21.62 87.43,20.19 v2(87.43,16.76)
SARADC_VIN4: length 127.7
  TOP w0.127: v2(96.88,22.76) 96.95,22.68 97.61,22.68 99.06,24.13 99.06,30.99 99.95,31.88 99.95,43.05 102.87,45.97 115.61,45.97 117.01,47.37 129.11,47.37 130.3,46.18 130.3,41.66 130.56,41.4 131.37,41.4 R60.2 135.89,42.04 136.27,41.66 136.27,40.51 136.88,39.91 D36.1 137.7,39.12 138.94,39.12 141.1,36.96 J13.4 ; M5.17 53.39,25.32 59.18,31.11 71.88,31.11 v2(72.77,32)
  BOTTOM w0.127: v2(96.88,22.76) 96.88,23.24 96.37,23.75 93.47,23.75 92.58,24.64 92.58,25.78 89.15,29.21 85.6,29.21 82.3,32.51 74.55,32.51 73.63,31.6 73.18,31.6 v2(72.77,32)
SARADC_VIN5: length 124
  TOP w0.127: v2(97.41,23.09) 97.43,23.11 97.66,23.11 98.81,24.26 98.81,31.11 99.69,32 99.69,43.18 102.74,46.23 115.47,46.23 116.87,47.62 129.46,47.62 130.76,46.33 130.76,44.88 132,43.64 R61.2 132,43.03 132.74,42.29 137.29,42.29 137.67,41.91 137.67,40.39 138.15,39.91 D37.1 139.04,39.91 139.95,38.99 142.06,38.99 ; M5.18 54.39,25.94 59.31,30.86 72.26,30.86 v2(73.41,32)
  BOTTOM w0.127: v2(73.41,32) 74.17,32.77 82.42,32.77 85.72,29.46 89.28,29.46 92.84,25.91 92.84,24.77 93.6,24 96.49,24 v2(97.41,23.09)
SATA1_RXN: length 18
  TOP w0.127: C50.1 44.96,78.87 44.96,78.51 49.3,74.17 56.72,74.17 58.04,75.49 58.04,76.44 J6.5
SATA1_RXP: length 17.3
  TOP w0.127: C51.1 45.21,78.87 45.21,78.61 49.4,74.42 56.61,74.42 57.78,75.59 57.78,76.56 57.42,76.92 J6.6
SATA1_TXN: length 11.3
  TOP w0.127: J6.3 61.57,77.43 61.57,78.11 61.44,78.23 54.2,78.23 53.52,78.92 53.52,79.53 53.39,79.65 v2(52.98,79.65)
  BOTTOM w0.127: C47.1 v2(52.98,79.65)
SATA1_TXP: length 11.3
  TOP w0.127: v2(54.31,79.65) 53.9,79.65 53.77,79.53 53.77,79.02 54.31,78.49 61.55,78.49 61.82,78.21 61.82,77.43 J6.2
  BOTTOM w0.127: C46.1 v2(54.31,79.65)
SCL_CAM: length 109.9
  TOP w0.127: v2(39.62,65.02) 39.37,64.77 39.37,64.01 40.13,63.25 65.28,63.25 68.71,66.67 77.09,66.67 77.85,65.91 88.27,65.91 89.53,64.64 93.73,64.64 95,63.37 95,53.85 95.25,53.59 95.25,49.4 94.87,49.02 94.87,42.97 v2(94.44,42.55) ; J28.7 23.18,60.8 v2(23.04,60.66)
  BOTTOM w0.127: v2(39.62,65.02) 38.48,65.02 36.07,67.44 36.07,69.14 35.48,69.72 28.7,69.72 24.26,65.28 24.26,63.47 23.67,62.88 23.67,61.29 v2(23.04,60.66) ; R144.2 v2(94.44,42.55)
SD_CLK: length 42.6
  TOP w0.127: v2(123.29,17.88) D9.1 123.29,17.12 123.71,16.7 123.86,16.7 124.53,16.03 J3.5
  BOTTOM w0.127: R21.2 C34.2 97.74,29.82 98.22,29.34 103.82,29.34 106.87,26.29 115.57,26.29 119.89,21.97 122.17,21.97 122.36,21.78 122.36,21.15 122.53,20.98 123.16,20.98 123.32,20.83 123.32,20.57 123.19,20.45 122.43,20.45 122.3,20.32 122.3,20.07 122.43,19.94 123.19,19.94 123.32,19.81 123.32,19.56 123.19,19.43 122.43,19.43 122.3,19.3 122.3,19.05 122.43,18.92 123.19,18.92 123.32,18.8 123.32,18.54 123.19,18.41 122.56,18.41 122.43,18.29 122.43,18.01 122.56,17.88 v2(123.29,17.88)
SD_CMD: length 46.2
  TOP w0.127: v2(126.75,17.2) D7.1 127.41,16.46 126.73,15.78 J3.3
  BOTTOM w0.127: v2(126.75,17.2) 126.75,17.65 126.87,17.78 128.78,17.78 128.91,17.91 128.91,18.16 128.78,18.29 126.75,18.29 126.62,18.41 126.62,19.81 123.06,23.37 120.14,23.37 114.3,29.21 114.3,30.1 113.54,30.86 107.82,30.86 106.43,32.26 99.06,32.26 98.42,31.62 R20.2
SD_D0: length 5.9
  TOP w0.127: J3.7 122.33,15.72 D3.1 121.62,17.96 R22.2
SD_D1: length 6.3
  TOP w0.127: J3.8 121.23,15.8 120.78,16.26 120.42,16.26 D4.1 120.24,17.96 R23.2
SD_D2: length 5.8
  TOP w0.127: J3.1 128.93,16.33 D5.1 130.3,17.71 130.3,19.03 R18.2
SD_D3: length 5.8
  TOP w0.127: J3.2 127.83,16.4 D6.1 129.18,17.76 129.18,18.98 R19.2
SDA_CAM: length 106.4
  TOP w0.127: v2(23.09,61.77) 23.09,61.7 23.48,61.3 J28.8 ; v2(39.5,65.66) 39.12,65.28 39.12,63.88 40.01,62.99 65.41,62.99 68.83,66.42 76.96,66.42 77.72,65.66 88.14,65.66 89.41,64.39 93.6,64.39 94.74,63.25 94.74,53.72 95,53.47 95,49.53 94.44,48.97 v2(94.44,43.69)
  BOTTOM w0.127: v2(39.5,65.66) 38.23,65.66 36.32,67.56 36.32,69.24 35.59,69.98 28.6,69.98 28.45,69.83 24,65.38 24,63.83 23.11,62.94 23.11,61.85 23.09,61.82 v2(23.09,61.77) ; R145.2 v2(94.44,43.69)
SDMMC0_CLK: length 1.8
  TOP w0.127: M5.63 95.65,29.24 v2(95.25,29.64)
  BOTTOM w0.127: v2(95.25,29.64) 95.45,29.84 R21.1
SDMMC0_CMD: length 3.4
  TOP w0.127: M5.64 95.74,30.24 94.89,31.09 94.89,31.22 v2(94.61,31.5)
  BOTTOM w0.127: v2(94.61,31.5) 95.12,31.5 95.25,31.62 R20.1
SDMMC0_D0: length 42.6
  TOP w0.127: M5.68 94.69,34.24 93.85,33.4 93.85,30.86 v2(93.34,30.35) ; R22.1 v2(121.62,20.88)
  BOTTOM w0.127: v2(93.34,30.35) 93.98,30.35 94.3,30.04 94.3,29.68 94.44,29.54 94.44,29.54 95.14,28.83 103.61,28.83 106.66,25.78 115.32,25.78 119.76,21.34 121.03,21.34 121.16,21.21 121.16,19.18 121.28,19.05 121.54,19.05 121.67,19.18 121.67,20.83 v2(121.62,20.88)
SDMMC0_D1: length 42.2
  TOP w0.127: v2(93.73,29.84) 94.11,30.23 94.11,33.15 94.49,33.53 94.99,33.53 95.28,33.24 M5.67 ; R23.1 v2(120.24,20.88)
  BOTTOM w0.127: v2(93.73,29.84) 95,28.57 103.5,28.57 106.55,25.53 115.19,25.53 119.38,21.34 119.38,19.43 119.51,19.3 120.65,19.3 120.78,19.43 120.78,19.68 120.65,19.81 120.02,19.81 119.89,19.94 119.89,20.19 120.02,20.32 120.65,20.32 120.78,20.45 120.78,20.71 120.61,20.88 v2(120.24,20.88)
SDMMC0_D2: length 42
  TOP w0.127: M5.66 95.14,32.24 v2(95.12,32.26) ; R18.1 v2(129.29,20.39)
  BOTTOM w0.127: v2(129.29,20.39) 128.83,19.94 127,19.94 123.32,23.62 120.4,23.62 120.01,24.01 119.99,24.01 119.61,24.38 119.61,24.41 114.68,29.34 114.68,30.23 113.79,31.11 108.2,31.11 106.68,32.64 98.93,32.64 98.42,32.13 95.64,32.13 95.52,32.26 v2(95.12,32.26)
SDMMC0_D3: length 42.8
  TOP w0.127: v2(94.74,32.77) 94.46,32.49 94.46,32.28 95,31.75 95.23,31.75 95.74,31.24 M5.65 ; R19.1 v2(128.14,20.39)
  BOTTOM w0.127: v2(94.74,32.77) 95.38,32.77 95.76,32.38 98.3,32.38 98.81,32.89 106.81,32.89 108.33,31.37 114.05,31.37 115.06,30.35 115.06,29.46 119.86,24.67 119.86,24.49 120.09,24.26 120.27,24.26 120.65,23.88 123.44,23.88 126.93,20.39 v2(128.14,20.39)
SDMMC0_DET_L: length 29.6
  TOP w0.127: R24.1 v2(118.87,20.88) ; M5.62 94.77,28.24 v2(94.69,28.32)
  BOTTOM w0.127: v2(94.69,28.32) 103.38,28.32 106.43,25.27 114.99,25.27 118.87,21.39 v2(118.87,20.88)
SDMMC2_CLK_M0: length 2.9
  TOP w0.127: v2(97.74,57.81) 97.49,58.06 97.2,58.06 97.03,58.24 M5.92
  BOTTOM w0.127: R159.1 98.35,58.42 v2(97.74,57.81)
SDMMC2_CMD_M0: length 26.8
  TOP w0.127: R157.2 v2(113.13,63.75) R158.1 ; M5.93 96.9,59.24 97.23,59.56 98.04,59.56 98.15,59.46 98.15,59.16 98.04,59.05 97.41,59.05 97.28,58.93 97.28,58.67 97.41,58.55 98.02,58.55 98.15,58.42 v2(98.15,57.1)
  BOTTOM w0.127: v2(98.15,57.1) 98.32,57.28 98.91,57.28 99.54,56.64 108.58,56.64 113.13,61.19 v2(113.13,63.75)
SDMMC2_D0_M0: length 25.6
  TOP w0.127: M5.97 96.59,63.24 96.92,62.91 96.92,62.84 99.19,60.58 99.19,58.17 99.69,57.66 v2(99.69,57.15) ; v2(111.48,61.09) 111.48,62.46 110.77,63.17 R153.1 R152.2
  BOTTOM w0.127: v2(111.48,61.09) 111.48,59.92 108.46,56.9 99.95,56.9 v2(99.69,57.15)
SDMMC2_D1_M0: length 23.2
  TOP w0.127: v2(110.52,60.93) 110.11,61.34 110.11,62.68 109.63,63.17 R154.1 ; v2(99.26,57.51) 98.93,57.84 98.93,60.32 97.41,61.85 96.98,61.85 96.59,62.24 M5.96
  BOTTOM w0.127: v2(110.52,60.93) 110.52,59.33 108.33,57.15 100.84,57.15 100.33,57.66 99.42,57.66 v2(99.26,57.51)
SDMMC2_D2_M0: length 27
  TOP w0.127: v2(115.06,62.89) 115.19,62.89 R155.1 ; M5.95 97.51,61.24 98.68,60.07 98.68,57.51 99.09,57.1 99.09,56.52 v2(98.88,56.31)
  BOTTOM w0.127: v2(98.88,56.31) 99.06,56.13 108.84,56.13 115.06,62.36 v2(115.06,62.89)
SDMMC2_D3_M0: length 26.7
  TOP w0.127: R156.1 113.79,62.56 v2(113.79,62.48) ; v2(98.65,56.85) 98.65,57.15 98.42,57.38 98.42,59.94 98.3,60.07 98.04,60.07 97.82,59.84 97.64,59.84 97.44,60.04 97.44,60.22 97.66,60.45 97.66,60.71 97.41,60.96 97.16,60.96 97.03,60.83 97.03,60.58 96.69,60.24 M5.94
  BOTTOM w0.127: v2(113.79,62.48) 113.79,61.47 108.71,56.39 99.42,56.39 98.96,56.85 v2(98.65,56.85)
SIM_CLK: length 22.2
  TOP w0.127: v2(119.25,31.75) 118.94,31.44 U36.32 ; R327.2 113.73,38.15 113.92,37.96 113.92,36.83 112.65,35.56 112.65,32.26 113.44,31.47 117.45,31.47 v2(117.47,31.45)
  BOTTOM w0.127: SIM1.C3 119.56,30.06 120.75,31.26 120.75,32.29 ; 120.75,32.29 D95.1 ; 120.75,32.29 120.02,32.29 119.97,32.34 C271.2 119.59,32.34 119.25,32 v2(119.25,31.75) 119.25,31.36 119.01,31.11 117.81,31.11 v2(117.47,31.45)
SIM_DATA: length 69.8
  TOP w0.127: v2(130.18,16.26) 130.18,7.37 129.54,6.73 v2(119.56,6.73) ; R339.1 110.77,37.29 111.2,37.72 111.43,37.72 111.86,38.15 R326.2 111.89,38.57 112.3,38.99 114.17,38.99 114.68,38.48 114.68,36.83 113.16,35.31 113.16,32.51 113.74,31.93 118.19,31.93 v2(118.49,31.62) 118.44,31.57 U36.34
  BOTTOM w0.127: SIM1.C7 v2(119.56,6.73) ; v2(118.49,31.62) 118.49,32 118.62,32.13 C262.2 118.03,32.34 117.98,32.29 D96.1 117.2,32.29 116.48,31.57 116.48,30.78 117.98,29.29 117.98,27.56 120.27,25.27 129.54,25.27 130.18,24.64 v2(130.18,16.26)
SIM_RST: length 21.6
  TOP w0.127: v2(115.19,32.89) 115.82,32.26 120.65,32.26 v2(121.41,31.5) 121.31,31.39 119.68,31.39 119.44,31.15 U36.30
  BOTTOM w0.127: v2(115.19,32.89) 115.19,33.29 114.87,33.61 R330.1 R329.2 ; v2(121.41,31.5) 121.41,33.76 121.9,34.24 C272.2 D94.1 121.94,33.12 122.56,32.51 122.56,30.52 122.1,30.06 SIM1.C2
SPI3_CLK_M1: length 122.7
  TOP w0.127: M5.27 63.39,23.1 64.14,22.35 66.17,22.35 67.87,20.65 83.88,20.65 88.95,20.65 89.41,20.19 98.3,20.19 101.09,22.99 101.09,29.97 101.98,30.86 101.98,42.04 103.89,43.94 116.59,43.94 117.98,45.34 127.28,45.34 128.14,44.48 128.14,37.97 130.94,35.18 130.94,31.37 136.78,25.53 136.78,20.04 D98.1 139.65,18.39 J14.3
SPI3_CS0_M1: length 113.8
  TOP w0.127: J14.6 139.27,24.86 D101.1 138.43,24.89 137.92,25.4 137.92,26.29 132.05,32.16 132.05,35.61 129.03,38.63 129.03,45.06 127.99,46.1 117.6,46.1 116.2,44.7 103.5,44.7 101.22,42.42 101.22,31.24 100.33,30.35 100.33,23.37 97.92,20.95 89.79,20.95 89.28,21.46 68.2,21.46 67.34,22.33 67.34,23.01 67.39,23.07 M5.31
SPI3_MISO_M1: length 116.2
  TOP w0.127: M5.30 66.39,22.89 68.07,21.21 89.15,21.21 89.66,20.7 98.04,20.7 100.58,23.24 100.58,30.23 101.47,31.11 101.47,42.29 103.63,44.45 116.33,44.45 117.73,45.85 127.75,45.85 128.78,44.82 128.78,38.43 131.7,35.51 131.7,31.88 137.54,26.04 137.54,23.59 D100.1 139.4,22.71 J14.5
SPI3_MOSI_M1: length 120.1
  TOP w0.127: J14.4 139.52,20.55 D99.1 137.16,21.82 137.16,25.78 131.32,31.62 131.32,35.41 128.52,38.2 128.52,44.55 127.48,45.59 117.86,45.59 116.46,44.2 103.76,44.2 101.73,42.16 101.73,30.97 100.84,30.08 100.84,23.11 98.17,20.45 89.53,20.45 89.08,20.9 84.9,20.9 68,20.9 66.29,22.61 64.59,22.61 64.39,22.8 M5.28
SPK_5V: length 6.9
  BOTTOM w0.508: U13.4 100.28,12.24 100.9,11.62 C93.2 ; L21.2 103.12,21.86 C92.2 100.28,20.64 U13.13
SPK_CTL_H_: length 2.2
  BOTTOM w0.508: U13.12 99.01,20.52 99.52,21.03 Q1.3
SPK_MUTE_H_: length 5
  BOTTOM w0.381: Q2.3 99.87,9.82 99.87,11.38 99.01,12.24 U13.5
SYS_LED_GPIO0_C7: length 109.8
  TOP w0.127: M5.26 62.39,25.18 64.01,26.8 65.28,26.8 67.56,29.08 69.09,29.08 69.85,29.84 74.55,29.84 76.58,31.88 76.58,56.64 72.01,61.21 38.61,61.21 37.85,61.98 37.85,65.02 v2(37.08,65.79) ; v2(35.56,69.09) 34.8,69.09 28.96,74.93 v2(28.96,77.72)
  BOTTOM w0.127: v2(37.08,65.79) 35.56,67.31 v2(35.56,69.09) ; R8.1 25.83,80.85 v2(28.96,77.72)
TP_INT: length 5.2
  BOTTOM w0.127: J24.4 74.32,23.12 74.19,23.24 D64.1 73.66,24.44 73.66,25.86 R112.2
TP_INT_L_GPIO3_B4: length 67.7
  TOP w0.127: M5.115 82.39,70.24 81.38,71.25 80.37,71.25 80.24,71.37 79.42,71.37 79.19,71.6 78.28,71.6 78.11,71.78 v2(77.86,71.78) ; v2(76.73,65.13) 76.83,65.02 78.36,65.02 79.25,64.14 85.34,64.14 86.61,62.87 86.61,35.05 79.38,27.81 76.2,27.81 75.69,27.3 74.68,27.3 v2(74.19,27.79)
  BOTTOM w0.127: R112.1 v2(74.19,27.79) ; v2(77.86,71.78) 77.86,71.74 77.93,71.68 77.93,69.16 76.73,67.97 v2(76.73,65.13)
TP_RST: length 5.4
  BOTTOM w0.127: R111.2 74.93,25.88 74.93,24.41 D65.1 75.44,23.5 74.82,22.87 J24.5
TP_RST_L_GPIO3_B3: length 65.5
  TOP w0.127: v2(76.96,71.51) 77.46,71.51 77.62,71.35 79.09,71.35 79.32,71.12 80.14,71.12 80.26,70.99 81.26,70.99 81.39,70.87 M5.116 ; v2(75.44,27.71) 75.79,28.07 79.25,28.07 86.36,35.18 86.36,62.74 85.22,63.88 79.12,63.88 78.36,64.64 76.58,64.64 76.33,64.9 v2(76.33,65.53)
  BOTTOM w0.127: v2(76.96,71.51) 76.96,69.47 76.33,68.83 v2(76.33,65.53) ; R111.1 v2(75.44,27.71)
TP_SCL: length 5.5
  BOTTOM w0.127: R113.2 72.52,25.91 72.52,24.41 D63.1 73.03,23.5 73.82,22.7 J24.3
TP_SDA: length 5.7
  BOTTOM w0.127: J24.2 73.32,22.47 D62.1 71.37,24.41 71.37,25.86 R114.2
UART0_RX: length 137.5
  TOP w0.127: v2(16.54,57.78) R372.1 17.6,59.49 16.89,60.2 16.89,62.61 16.03,63.47 16.03,69.65 19.94,73.56 29.82,73.56 34.29,69.09 v2(34.29,68.96) ; M5.19 55.39,25.04 60.71,30.35 74.3,30.35 76.07,32.13 76.07,56.39 71.83,60.63 38.35,60.63 37.08,61.9 v2(37.08,64.52)
  BOTTOM w0.127: R383.1 13.41,57.58 13.61,57.78 v2(16.54,57.78) ; v2(37.08,64.52) 35.05,66.55 35.05,68.2 v2(34.29,68.96)
UART0_RX_: length 1.7
  TOP w0.127: U27.9 19.06,57.92 18.92,57.78 R372.2
UART0_TX: length 135.9
  TOP w0.127: U27.10 18.34,59.64 v2(17.37,60.6) 17.27,60.71 17.27,62.92 16.38,63.8 16.38,69.47 20.19,73.28 29.46,73.28 v2(33.66,69.09) ; M5.20 56.39,24.77 61.72,30.1 74.42,30.1 76.33,32 76.33,56.52 71.91,60.93 38.51,60.93 37.59,61.85 37.59,64.64 v2(37.08,65.15)
  BOTTOM w0.127: v2(17.37,60.6) 17.09,60.33 15.11,60.33 14.35,61.09 R278.1 ; v2(33.66,69.09) 34.04,69.47 34.54,69.47 35.31,68.71 35.31,66.93 v2(37.08,65.15)
UART2_RX_M0: length 12.2
  TOP w0.127: R26.1 102.69,20.37 102.36,20.7 102.36,21.34 102.74,21.72 102.74,23.51 v2(101.6,24.65) ; v2(97.13,25.91) 96.8,26.24 M5.60
  BOTTOM w0.127: v2(101.6,24.65) 98.39,24.65 v2(97.13,25.91)
UART2_TX_M0: length 10.3
  TOP w0.127: R27.1 103.63,23.37 v2(102.74,24.26) ; M5.59 v2(97.13,25.24)
  BOTTOM w0.127: v2(97.13,25.24) 98.11,24.26 v2(102.74,24.26)
UART3_RX_M1: length 81
  TOP w0.127: R370.1 21.77,68.53 v2(20.83,69.47) ; v2(39.88,79.76) 40.13,79.76 41.78,78.11 42.67,78.11 48.9,71.88 66.22,71.88 67.36,73.03 70.74,73.03 70.99,72.77 85.17,72.77 86.39,71.55 M5.111
  BOTTOM w0.127: v2(20.83,69.47) 21.21,69.09 22.73,69.09 30.23,76.58 38.86,76.58 39.12,76.83 39.12,78.99 v2(39.88,79.76)
  BOTTOM w0.203: v2(20.83,69.47) 20.8,69.44 19.94,69.44 19.48,68.99 R384.1
UART3_RX_M1_: length 1.9
  TOP w0.127: U26.12 19.97,67.65 20.14,67.82 R370.2
UART3_TX_M1: length 79.6
  TOP w0.127: v2(39.88,79.12) 40.39,79.12 41.66,77.85 42.55,77.85 48.77,71.63 66.34,71.63 67.49,72.77 70.61,72.77 70.87,72.52 83.69,72.52 85.39,70.82 M5.112 ; U26.11 19.88,67 v2(20.19,67.31)
  BOTTOM w0.127: v2(20.19,67.31) 21.72,68.83 22.86,68.83 30.35,76.33 38.99,76.33 39.37,76.71 39.37,78.61 v2(39.88,79.12)
  BOTTOM w0.203: v2(20.19,67.31) 19.68,67.82 R282.1
UART4_RX_M1: length 74
  TOP w0.127: v2(40.39,77.98) 41.02,77.34 42.29,77.34 48.51,71.12 66.6,71.12 67.74,72.26 70.36,72.26 70.61,72.01 75.44,72.01 76.61,70.84 78.88,70.84 79.39,70.33 M5.118 ; R371.1 21.77,65.54 21.08,66.22 v2(21.08,66.93)
  BOTTOM w0.127: v2(40.39,77.98) 40.64,77.72 40.64,75.95 39.75,75.06 29.84,75.06 23.11,68.33 22.35,68.33 21.08,67.06 v2(21.08,66.93) 19.53,65.38 19.04,65.38
  BOTTOM w0.203: 19.04,65.38 18.64,65.38 R385.1
UART4_RX_M1_: length 2
  TOP w0.127: U26.9 20.06,65.69 20.35,65.41 R371.2
UART4_TX_M1: length 74.1
  TOP w0.127: v2(39.88,78.49) 40.64,78.49 41.53,77.6 42.42,77.6 48.64,71.37 66.47,71.37 67.61,72.52 70.48,72.52 70.74,72.26 75.56,72.26 76.73,71.09 78.98,71.09 79.21,70.87 80.01,70.87 80.39,70.49 M5.117 ; U26.10 19.86,66.34 v2(20.19,66.67)
  BOTTOM w0.127: R284.1 19.18,66.55 19.3,66.67 v2(20.19,66.67) 22.1,68.58 22.99,68.58 29.72,75.31 38.73,75.31 39.88,76.45 v2(39.88,78.49)
UART5_RX_M1: length 101.2
  TOP w0.127: v2(40.51,80.39) 40.51,80.14 42.04,78.61 42.93,78.61 49.15,72.39 65.96,72.39 67.11,73.53 70.61,73.53 70.89,73.81 71.73,73.81 72.26,73.28 87.5,73.28 89.39,71.39 M5.108 ; v2(21.97,52.96) 21.97,57.15 22.48,57.66 22.48,58.88 21.77,59.59 R373.1 21.77,61.54 21.58,61.72 v2(20.94,61.72)
  BOTTOM w0.127: v2(20.94,61.72) 20.94,62.12 20.95,62.13 20.95,65.41 21.84,66.29 21.84,67.06 22.61,67.82 23.37,67.82 28.57,73.03 39.24,73.03 41.15,74.93 41.15,79.76 v2(40.51,80.39) ; D82.A 22.73,52.2 v2(21.97,52.96) 22.27,53.26 R287.2
UART5_RX_M1_: length 1.9
  TOP w0.127: R373.2 20.12,61.09 19.97,60.94 U27.12
UART5_TX_M1: length 96.2
  TOP w0.127: v2(39.88,80.39) 41.91,78.36 42.82,78.36 49.04,72.14 66.09,72.14 67.23,73.28 70.87,73.28 71.12,73.03 87.25,73.03 88.39,71.89 M5.109 ; v2(20.19,60.45) 20.03,60.29 U27.11
  BOTTOM w0.127: R286.1 R288.1 20.41,58.95 D84.C 20.88,59.5 20.49,59.88 20.49,60.15 v2(20.19,60.45) 20.19,61.72 20.7,62.23 20.7,65.53 21.59,66.42 21.59,67.18 22.48,68.07 23.24,68.07 29.21,74.04 39.88,74.04 40.89,75.06 40.89,79.38 v2(39.88,80.39)
UART7_RX_M1: length 108.3
  TOP w0.127: M5.106 91.39,70.33 87.93,73.79 72.62,73.79 72.09,74.32 70.59,74.32 70.31,74.04 66.82,74.04 65.68,72.9 49.4,72.9 43.18,79.12 42.29,79.12 41.27,80.14 v2(41.27,81.03) ; v2(20.57,56.9) 21.59,57.91 v2(21.59,59.05)
  BOTTOM w0.127: v2(20.57,56.9) 20.57,53.59 21.97,52.2 21.97,51.56 22.48,51.05 22.48,47.8 22.4,47.73 R294.2 22.4,46.62 22.54,46.48 D86.A ; v2(41.27,81.03) 41.66,80.64 41.66,73.91 39.61,71.87 28.23,71.87 21.46,65.11 21.46,62.23 21.59,62.1 v2(21.59,59.05)
UART7_TX_M1: length 106.7
  TOP w0.127: v2(40.64,81.03) 41.02,80.64 41.02,80.01 42.16,78.87 43.05,78.87 49.28,72.64 65.79,72.64 66.93,73.79 70.43,73.79 70.71,74.07 71.88,74.07 72.42,73.53 87.65,73.53 90.39,70.79 M5.107 ; v2(20.95,60.33) 20.95,59.18 17.4,55.63 17.4,53.34 16.89,52.83 16.89,51.41 v2(17.05,51.26)
  BOTTOM w0.127: R291.1 16.08,50 D88.C 17.05,50.97 v2(17.05,51.26) 17.02,51.28 17.02,51.77 R295.1 ; v2(40.64,81.03) 41.4,80.26 41.4,74.04 39.48,72.12 28.05,72.12 23.5,67.56 22.73,67.56 22.1,66.93 22.1,66.17 21.21,65.28 21.21,62.1 21.34,61.98 21.34,61.1 20.95,60.72 v2(20.95,60.33)
UART8_CTSN_M0: length 49.8
  TOP w0.127: U23.41 113.2,48.18 112.78,47.75 104.57,47.75 R173.1 103.55,47.75 101.98,47.75 98.17,43.94 98.17,33.03 v2(97.92,32.78) ; v2(89.52,32.8) 89.52,32.25 83.34,26.06 83.34,25.33 82.39,24.38 M5.46
  BOTTOM w0.127: v2(89.52,32.8) 89.99,33.27 95.5,33.27 96,32.78 v2(97.92,32.78)
UART8_RTSN_M0: length 57
  TOP w0.127: U23.44 115.9,48.21 114.68,46.99 102.36,46.99 98.93,43.56 98.93,32.38 98.04,31.5 98.04,24.64 97.41,24 96.39,24 94.74,22.35 93.22,22.35 92.91,22.66 81.74,22.66 81.39,23.01 M5.45
UART8_RX_M0: length 41.1
  TOP w0.127: M5.58 94.39,24.03 94.87,24.51 97.16,24.51 97.54,24.89 97.54,31.75 98.42,32.64 98.42,43.81 102.11,47.5 113.41,47.5 114.1,48.19 U23.42
UART8_TX_M0: length 43.9
  TOP w0.127: M5.57 93.39,22.94 93.73,22.61 94.61,22.61 96.27,24.26 97.28,24.26 97.79,24.76 97.79,31.62 98.68,32.51 98.68,43.69 102.23,47.24 114.05,47.24 115,48.2 U23.43
USB2_HOST2_DM: length 11.1
  TOP w0.127: v2(89.54,66.07) 89.79,65.83 89.79,65.58 90.09,65.28 93.98,65.28 94.31,65.61 95.18,65.61 95.55,65.24 M5.99
  BOTTOM w0.127: v2(89.54,66.07) 89.79,65.83 89.79,63.86 89.35,63.42 89.18,63.42 R51.2
USB2_HOST2_DP: length 11.1
  TOP w0.127: M5.100 95.55,66.24 95.18,65.86 94.2,65.86 93.87,65.53 90.2,65.53 90.04,65.69 90.04,65.83 v2(90.29,66.07)
  BOTTOM w0.127: R50.2 89.18,63.17 89.46,63.17 90.04,63.75 90.04,65.83 v2(90.29,66.07)
